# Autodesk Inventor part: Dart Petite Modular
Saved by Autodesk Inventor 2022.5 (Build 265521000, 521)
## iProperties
Created: 2025-01
Part Number: Dart Petite Modular
Material: Generic
Document SubType Name: Modeling
Designer: AdminForWorker
Density: 1 g/cm^3
Appearance: Default
Title: Dart Petite Modular
Author: AdminForWorker
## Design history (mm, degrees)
feature "Dart Petite Modular"
body "Solid1"
